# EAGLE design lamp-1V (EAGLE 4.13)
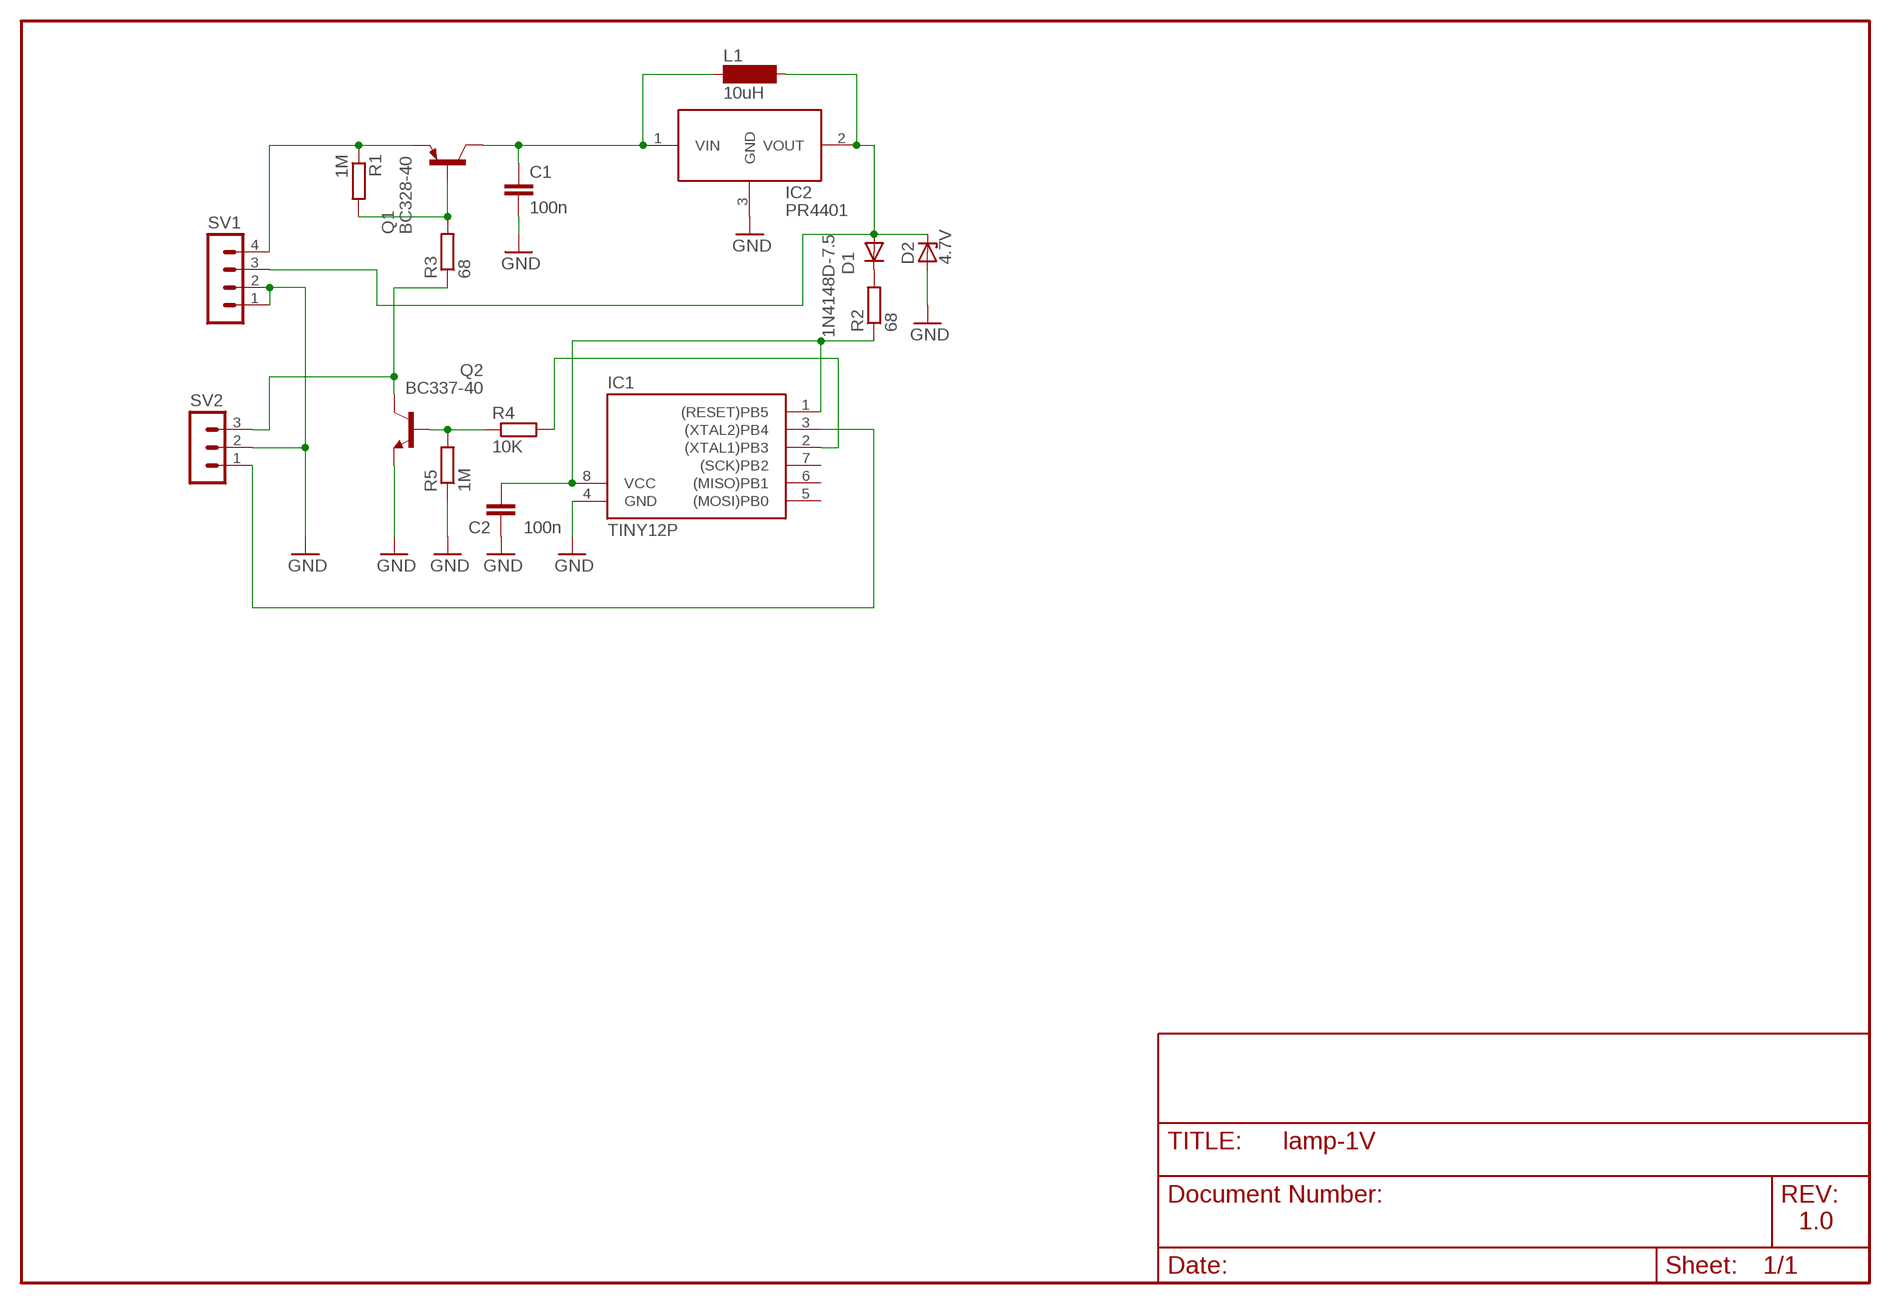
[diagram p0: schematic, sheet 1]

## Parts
C1  100n  C-EU025-024X044  [C025-024X044]
C2  100n  C-EU025-024X044  [C025-024X044]
D1  1N4148D-7.5  [D-7.5]
D2  4.7V  DIODE-ZENER1  [DO34Z7]
IC1  TINY12P  [DIL08]
IC2  PR4401  [SOT23]
L1  10uH  SPULE-SMD1  [MS50]
Q1  BC328-40  [TO92-EBC]
Q2  BC337-40  [TO92]
R1  1M  R-EU_0207/10  [0207/10]
R2  68  R-EU_0207/10  [0207/10]
R3  68  R-EU_0207/10  [0207/10]
R4  10K  R-EU_0207/10  [0207/10]
R5  1M  R-EU_0207/10  [0207/10]
SV1  MA04-1  [MA04-1]
SV2  MA03-1  [MA03-1]

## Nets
GND: C1.2 C2.1 D2.A IC1.4(GND) IC2.3(GND) Q2.1(E) R5.1 SV1.1 SV1.2 SV2.2
N$1: C2.2 IC1.1((RESET)PB5) IC1.8(VCC) R2.1
N$2: D1.C R2.2
N$3: Q2.2(B) R4.1 R5.2
N$4: Q1.E R1.1 SV1.4
N$5: C1.1 IC2.1(VIN) L1.1 Q1.C
N$6: D1.A D2.C IC2.2(VOUT) L1.2 SV1.3
N$7: IC1.2((XTAL1)PB3) R4.2
N$8: Q2.3(C) R3.1 SV2.3
N$9: Q1.B R1.2 R3.2
N$11: IC1.3((XTAL2)PB4) SV2.1
Unconnected: IC1.5((MOSI)PB0) IC1.6((MISO)PB1) IC1.7((SCK)PB2)

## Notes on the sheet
- 1.0

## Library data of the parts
C1 C2 = wm:C-EU: CAPACITOR, European symbol
D1 = wm:1N4148: DIODE
D2 = wm:DIODE-ZENER1: Z DIODE
IC1 = wm:TINY12*: MICROCONTROLLER 1 Kbytes FLASH 64 bytes EEPROM
IC2 = wm:PR4401
L1 = wm:SPULE-SMD1: INDUCTOR
Q1 = wm:BC328*: PNP Transistror
Q2 = wm:BC337*: NPN Transistor
R1-R5 = wm:R-EU_: RESISTOR, European symbol
SV1 = wm:MA04-1: PIN HEADER
SV2 = wm:MA03-1: PIN HEADER

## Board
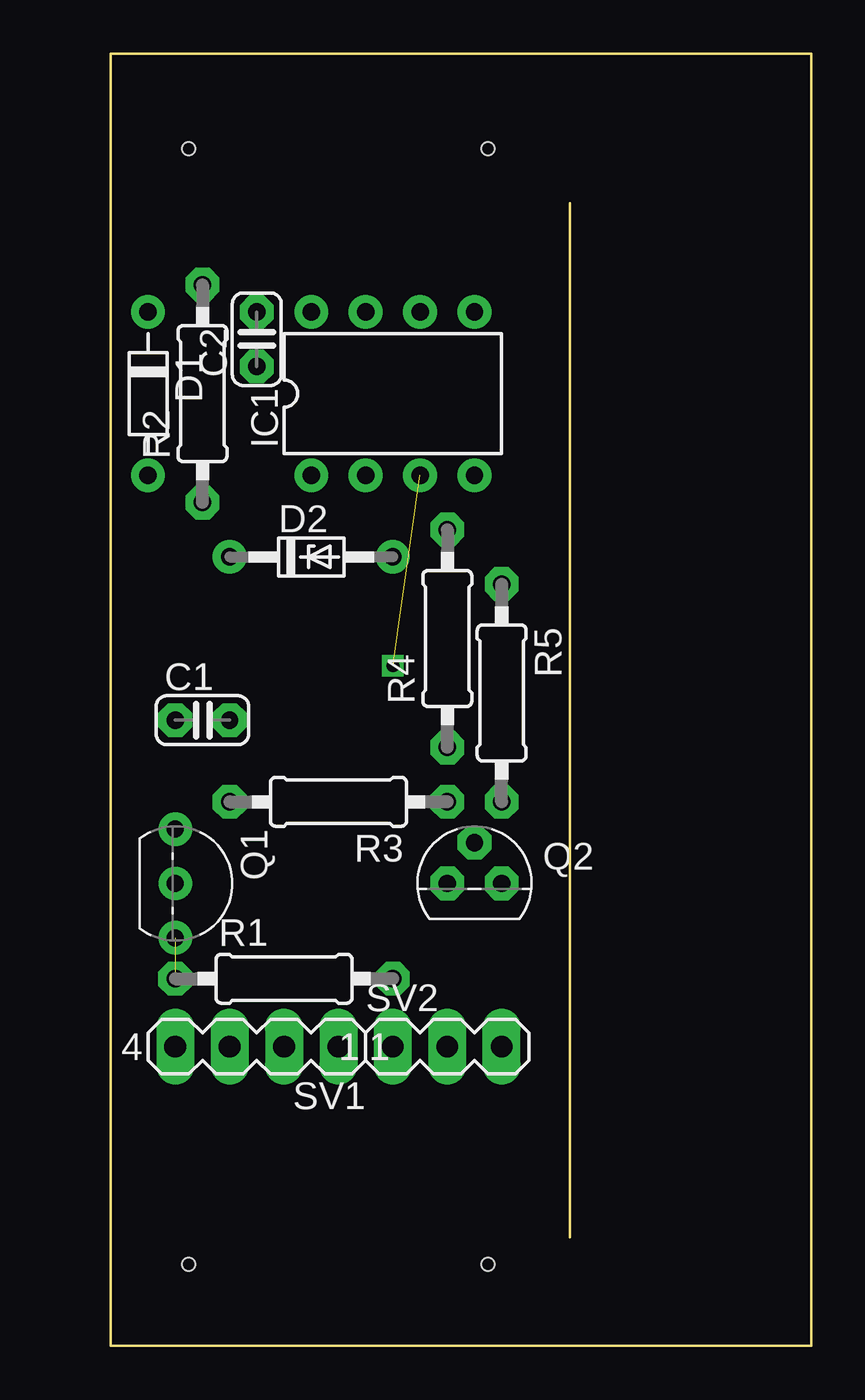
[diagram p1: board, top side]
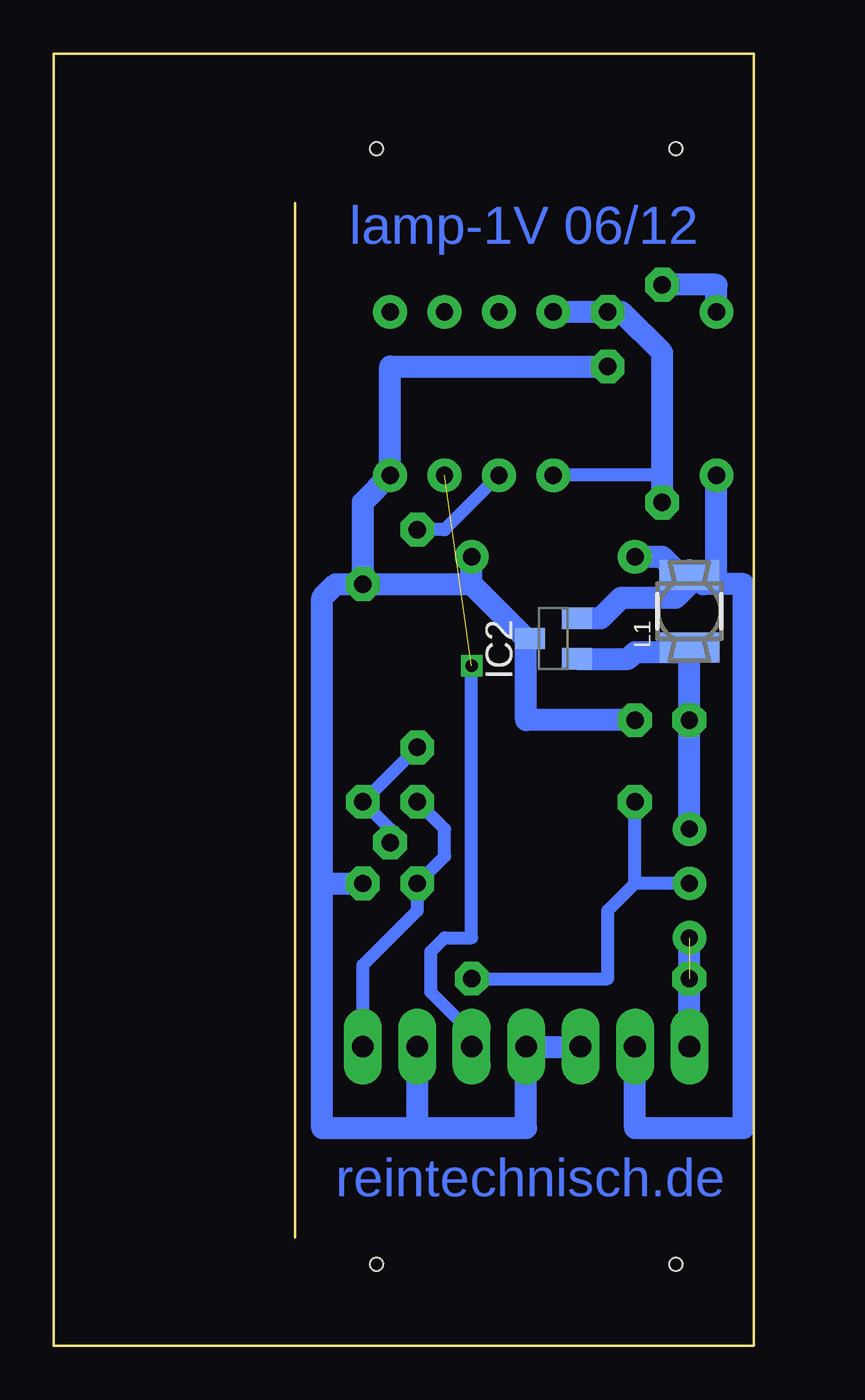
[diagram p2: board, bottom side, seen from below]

Size 32.69 x 60.31 mm. Coordinates in mm from the lower left corner, seen from the top.
Outline: 21.43,53.34 21.43,5.08
Outline: 0,0 32.69,0 32.69,60.31 0,60.31 0,0
Copper layers (1*16): Top 0.035mm / dielectric 1.5mm / Bottom 0.035mm
Design rules "default": minimum track width 10mil, minimum drill 24mil, track to track 8mil, track to pad 8mil, pad to pad 8mil, via to via 8mil, smd to smd 8mil, copper to edge 40mil, drill to drill 8mil, minimum pad ring 15mil, minimum via ring 8mil, stop-mask expansion 4mil, vias tented up to drill 0mil, thermal gap 10mil
Holes 0.6 mm at 17.62,55.88 3.65,55.88 3.65,3.81 17.62,3.81

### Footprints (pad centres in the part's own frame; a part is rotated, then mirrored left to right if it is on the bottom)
C025-024X044 = drill 0.813 octagon: 1 -1.27,0; 2 1.27,0
D-7.5 = drill 0.813 round: A 3.81,0; C -3.81,0
DO34Z7 = drill 0.813 round: A 3.81,0; C -3.81,0
DIL08 = drill 0.813 round: 1 -3.81,-3.81; 2 -1.27,-3.81; 3 1.27,-3.81; 4 3.81,-3.81; 5 3.81,3.81; 6 1.27,3.81; 7 -1.27,3.81; 8 -3.81,3.81
SOT23 = smd 1 x 1.4: 1 -0.95,-1.1; 2 0.95,-1.1; 3 0,1.1
MS50 = smd 2.8 x 1.4: 1 0,-1.7; 2 0,1.7
TO92-EBC = drill 0.8 round: B 0,-1.27; C -2.54,-1.27; E 2.54,-1.27
TO92 = drill 0.813 octagon: 1 1.27,0; 2 0,1.905; 3 -1.27,0
0207/10 = drill 0.813 octagon: 1 -5.08,0; 2 5.08,0
MA04-1 = drill 1.016 long: 1 -3.81,0; 2 -1.27,0; 3 1.27,0; 4 3.81,0
MA03-1 = drill 1.016 long: 1 -2.54,0; 2 0,0; 3 2.54,0

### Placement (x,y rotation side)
C1  4.28,29.21 0 top
C2  6.82,46.98 90 top
D1  1.74,44.45 270 top
D2  9.36,36.82 0 top
IC1  13.17,44.45 0 top
IC2  9.36,33.02 90 bottom
L1  3.01,34.28 0 bottom
Q1  4.28,21.59 270 top
Q2  16.98,21.59 0 top
R1  8.09,17.14 0 top
R2  4.28,44.45 90 top
R3  10.63,25.39 180 top
R4  15.71,33.02 90 top
R5  18.25,30.48 270 top
SV1  6.82,13.96 180 top
SV2  15.71,13.96 0 top

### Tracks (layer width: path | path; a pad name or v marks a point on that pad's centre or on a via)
GND
  Bottom 1.016: 15.71,10.15 SV2.2 | SV1.2 SV1.1 10.63,10.15 15.71,10.15 | 15.71,10.15 20.16,10.15 20.16,21.59 | R5.1 19.52,35.55 20.16,34.92 20.16,21.59 | R5.1 18.25,39.36 IC1.4 16.98,45.71 C2.1 | 13.17,35.55 D2.A | R5.1 13.17,35.55 | 20.16,21.59 Q2.1 | C1.2 10.63,29.21 10.63,33.02 | 10.63,33.02 IC2.3 | 10.63,33.02 13.17,35.55
N$1
  Bottom 0.61: 4.28,40.63 IC1.1
  Bottom 1.016: IC1.8 C2.2 6.18,48.25 4.28,46.35 4.28,40.63 R2.1
N$2
  Bottom 1.016: D1.C 1.74,49.52 R2.2
N$3
  Bottom 0.61: R4.1 R5.2 16.98,24.12 Q2.2
N$4  (1 unrouted)
  Bottom 1.016: SV1.4 Q1.E
N$5
  Bottom 0.61: L1.1 3.01,33.02
  Bottom 1.016: Q1.C C1.1 3.01,32.38 | IC2.1 5.87,32.06 5.55,32.38 3.01,32.38 | 3.01,32.38 L1.1
N$6
  Bottom 1.016: SV1.3 5.55,10.15 0.47,10.15 0.47,35.55 1.74,35.55 | 1.74,35.55 2.38,35.55 3.01,36.19 L1.2 3.01,35.55 | 1.74,35.55 D1.A | D2.C 4.28,36.82 3.01,35.55 | IC2.2 7.14,33.96 6.18,34.92 3.65,34.92 3.01,35.55
N$7
  Bottom 0.61: IC1.2 14.44,38.09 R4.2
N$8
  Bottom 0.61: SV2.3 18.25,17.78 15.71,20.32 Q2.3 14.44,22.86 14.44,24.12 R3.1
N$9
  Bottom 0.61: 5.55,21.59 6.82,20.32 6.82,17.14 R1.2 | Q1.B 5.55,21.59 | 5.55,21.59 R3.2
N$10  (via drill 0.6)
  other vias: 13.17,31.75
N$11  (1 unrouted)
  Bottom 0.61: SV2.1 13.17,14.6 15.08,16.51 15.08,18.41 14.44,19.05 13.17,19.05 13.17,31.75

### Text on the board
Bottom: lamp-1V 06/12 | reintechnisch.de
